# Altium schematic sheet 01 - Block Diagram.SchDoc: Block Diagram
size A3; PageSetup: Record=PageOptions¦CenterHorizontal=True¦CenterVertical=True¦PrintScale=0.70¦XCorrection=1.00¦YCorrection=1.00¦PrintKind=0¦BorderSize=5000000¦LeftOffset=0¦BottomOffset=0¦Orientation=2¦PaperLength=4200¦PaperWidth=2970¦Scale=100¦PaperSource=7¦PrintQuality=600¦MediaType=1¦DitherType=10¦PaperKind=A4¦PrintScaleMode=1; Author: Juan Anzola; SheetNumber: 1; SheetTotal: 21
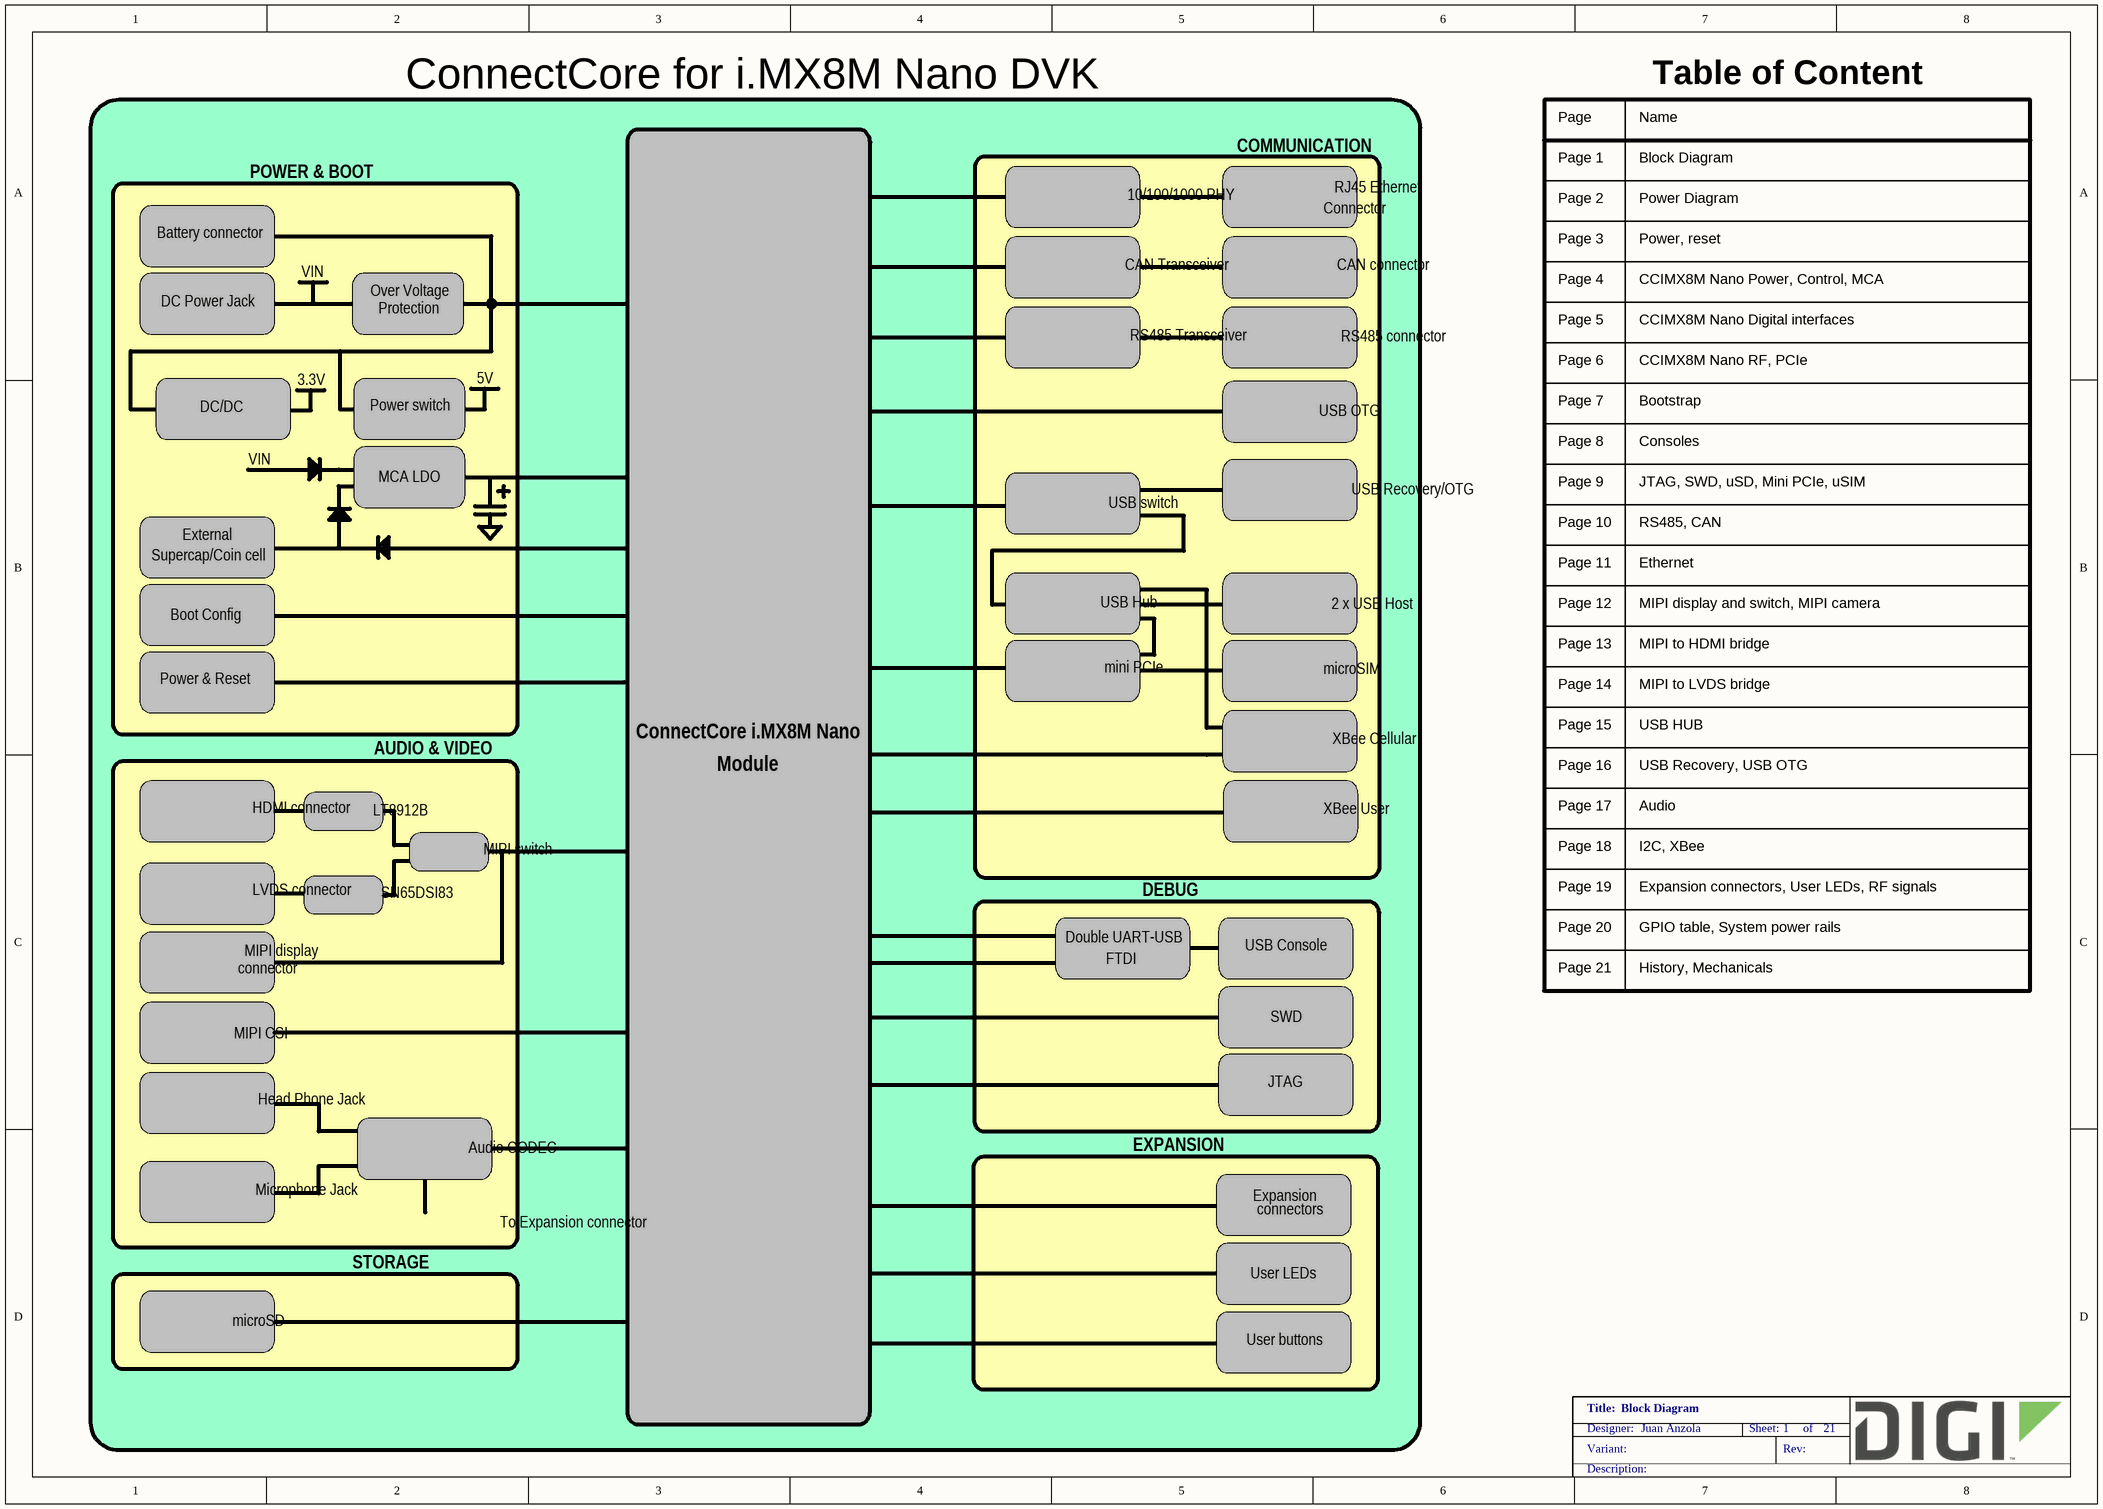
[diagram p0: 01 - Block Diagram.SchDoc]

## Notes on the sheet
- ConnectCore for i.MX8M Nano DVK
- Table of Content
- POWER & BOOT
- COMMUNICATION
- Page 1
- Page
- Block Diagram
- Name
- Battery connector
- 10/100/1000 PHY
- Connector
- RJ45 Ethernet
- Page 2
- Page 3
- Power, reset
- Power Diagram
- DC Power Jack
- VIN
- Protection
- Over Voltage
- CAN Transceiver
- CAN connector
- Page 4
- CCIMX8M Nano Power, Control, MCA
- 5V
- RS485 Transceiver
- RS485 connector
- Page 5
- Page 6
- CCIMX8M Nano Digital interfaces
- CCIMX8M Nano RF, PCIe
- DC/DC
- 3.3V
- Power switch
- USB OTG
- Page 7
- Page 8
- Consoles
- Bootstrap
- MCA LDO
- USB switch
- USB Recovery/OTG
- Page 9
- JTAG, SWD, uSD, Mini PCIe, uSIM
- Supercap/Coin cell
- External
- Page 10
- Page 11
- RS485, CAN
- Ethernet
- Boot Config
- USB Hub
- 2 x USB Host
- Page 12
- Page 13
- MIPI display and switch, MIPI camera
- MIPI to HDMI bridge
- Power & Reset
- mini PCIe
- microSIM
- Page 14
- MIPI to LVDS bridge
- AUDIO & VIDEO
- ConnectCore i.MX8M Nano
- Module
- XBee Cellular
- Page 15
- Page 16
- USB HUB
- USB Recovery, USB OTG
- HDMI connector
- LT8912B
- MIPI switch
- XBee User
- Page 17
- Page 18
- Audio
- I2C, XBee
- LVDS connector
- SN65DSI83
- DEBUG
- Page 19
- Expansion connectors, User LEDs, RF signals
- connector
- MIPI display
- Double UART-USB
- FTDI
- USB Console
- Page 20
- Page 21
- History, Mechanicals
- GPIO table, System power rails
- MIPI CSI
- SWD
- Head Phone Jack
- JTAG
- Audio CODEC
- EXPANSION
- Microphone Jack
- To Expansion connector
- Expansion
- connectors
- microSD
- STORAGE
- User LEDs
- User buttons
